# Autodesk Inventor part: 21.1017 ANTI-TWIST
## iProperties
Created: 2006-12
Part Number: 21.1017 ANTI-TWIST
Document SubType Name: Modeling
Designer: Andy Moles
Material: Steel
Mass: 7.91166 g
Surface Area: 13.6057 cm^2
Volume: 1.00786 cm^3
Density: 7.85 g/cm^3
Author: Andy Moles
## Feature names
1. Base1
